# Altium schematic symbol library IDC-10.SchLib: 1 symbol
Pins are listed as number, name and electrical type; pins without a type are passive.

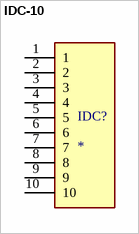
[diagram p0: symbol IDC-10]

## IDC-10
designator IDC?
Header, Pin, Idc, Amp-Latch, 10 Pos, Low Profile, Pcb, Vertical, Blue; MF: TE Connectivity; MP: 2-1761603-3; Centerline_Pitch: 2.54 mm[.1 in]; Product_Type: Connector; Number_of_Positions: 10
footprint IDC-10
pins: 1, 2, 3, 4, 5, 6, 7, 8, 9, 10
